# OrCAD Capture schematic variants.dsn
size A; title: EMA DESIGN AUTOMATION; rev: B; note: CIP DEMO
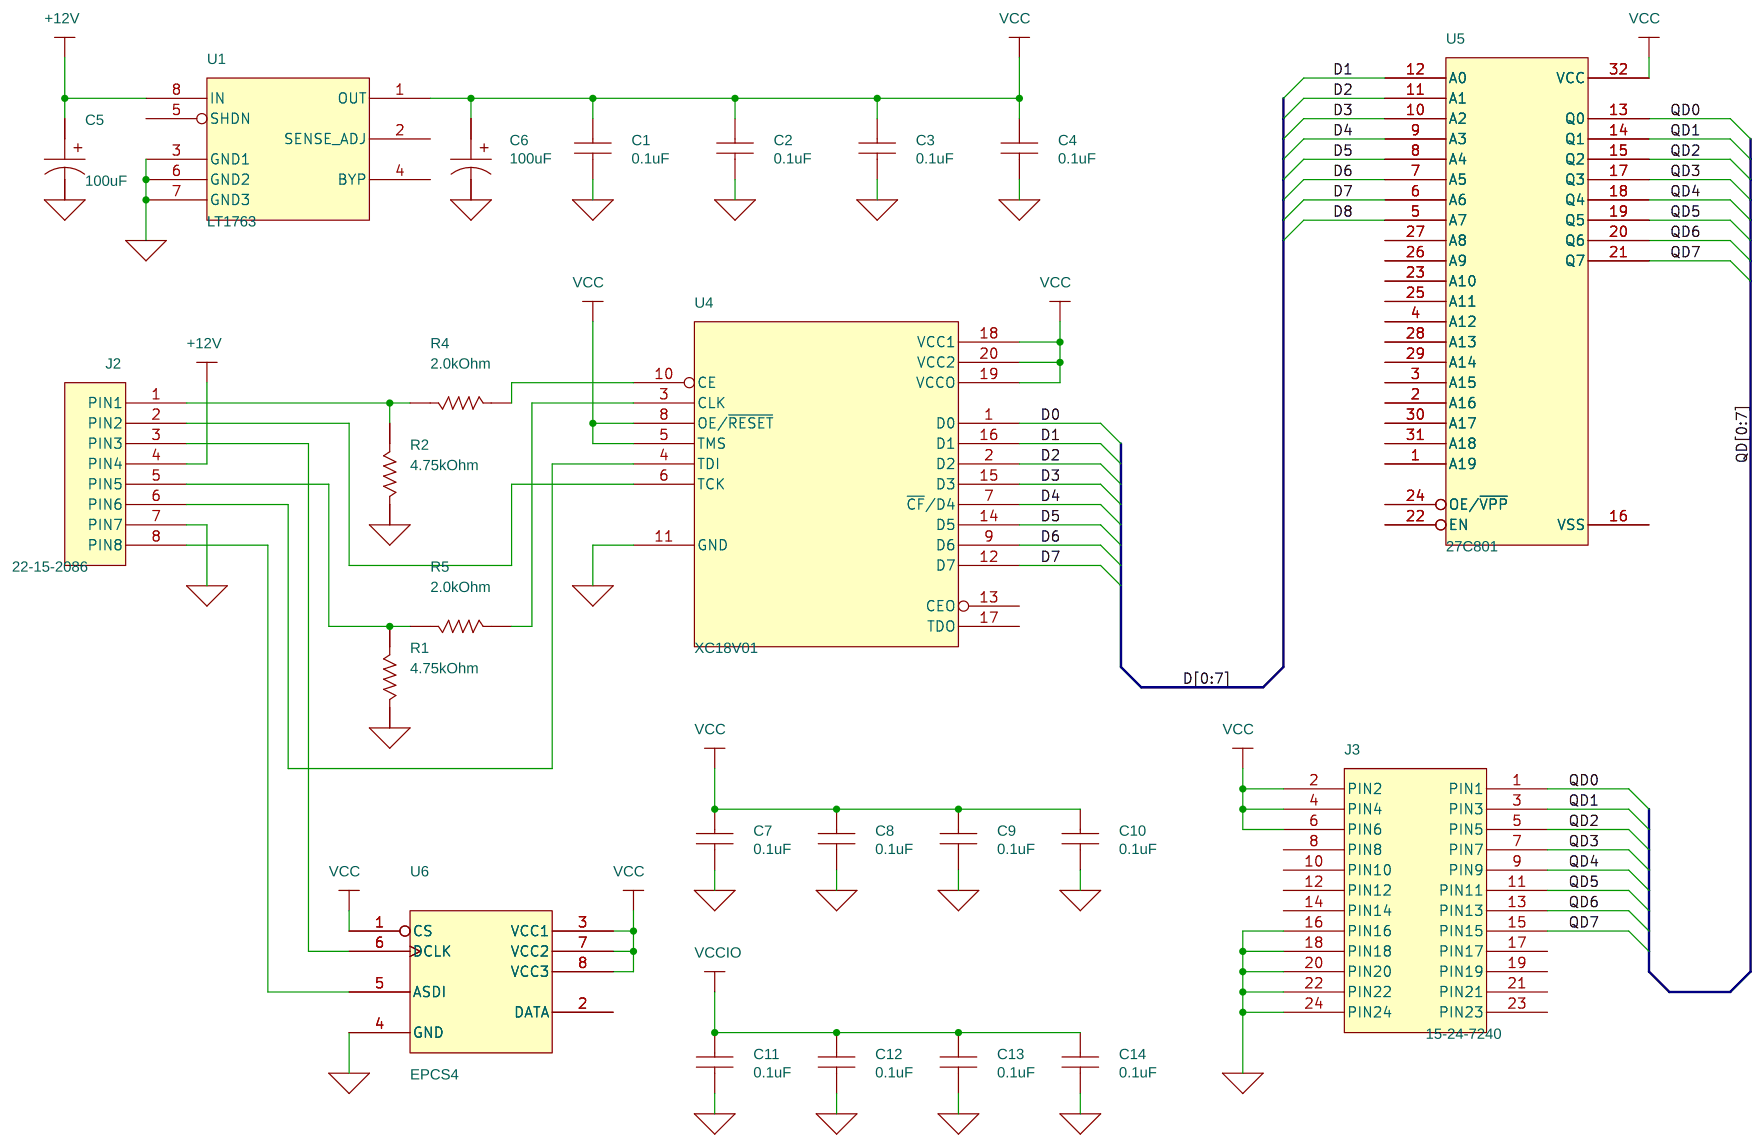
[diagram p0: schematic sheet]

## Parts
C1  0.1uF  [CAPC2012X71N]
C2  0.1uF  [CAPC2012X71N]
C3  0.1uF  [CAPC2012X71N]
C4  0.1uF  [CAPC2012X71N]
C5  100uF  [CAPMP6032X280N]
C6  100uF  [CAPMP6032X280N]
C7  0.1uF  [CAPC2012X71N]
C8  0.1uF  [CAPC2012X71N]
C9  0.1uF  [CAPC2012X71N]
C10  0.1uF  [CAPC2012X71N]
C11  0.1uF  [CAPC2012X71N]
C12  0.1uF  [CAPC2012X71N]
C13  0.1uF  [CAPC2012X71N]
C14  0.1uF  [CAPC2012X71N]
J2  22-15-2086  [MOLEX_4455A-8]
J3  15-24-7240  [MOLEX_42385-24]
R1  4.75kOhm  [RESC1608X55N]
R2  4.75kOhm  [RESC1608X55N]
R4  2.0kOhm  [RESC1608X55N]
R5  2.0kOhm  [RESC1608X55N]
U1  LT1763  [SOIC127P600X175-8N]
U4  XC18V01  [SOIC127P1034X267-20N]
U5  27C801  [DIP32-600]
U6  EPCS4  [SOIC127P600X175-8N]

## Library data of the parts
C1-C4 C7-C14 = CAP: CAP, Ceramic, SMD, 0.1 uF, 10 %, 25 V, 0805; CLASS: DISCRETE; Dielectric Type: Ceramic; Manufacturer: AVX; Manufacturer PN: 08053C104KAT2A; Operating Temperature Maximum: 125 C; Operating Temperature Minimum: -55 C; PART_NUMBER: EMA-00000403; Package Size: 0805; Rated Voltage: 25 V; Temperature Coefficient: X7R; Tolerance: 10%
C5 C6 = CAP_P: CAP, Tantalum, SMD, 100 uF, 10 %, 6.3 V, 6032-28; CLASS: DISCRETE; Dielectric Type: Tantalum; Manufacturer: AVX; Manufacturer PN: TPSC107K006R0150; Operating Temperature Maximum: 125 C; Operating Temperature Minimum: -55 C; PART_NUMBER: EMA-00000517; Package Size: 6032-28; Part Number: EMA-00007000; Rated Voltage: 6.3 V; Tolerance: 10%
J2 = CONN_PCB_1X8_F: CONN, Header, 22-15-2086, 8, TH; CLASS: IO; Contact Voltage: 250 V; Manufacturer: Molex Inc; Operating Temperature Maximum: 75 C; Operating Temperature Minimum: 0.0 C; PART_NUMBER: EMA-00006006; Package Size: 20.22 x 7.9 x 7.7 mm
J3 = HDR_2X12_F: CONN, Header, 15-24-7240, 24, TH; CLASS: IO; Contact Voltage: 600 V; Manufacturer: Molex Inc; Operating Temperature Maximum: 105 C; Operating Temperature Minimum: -40 C; PART_NUMBER: EMA-00005995; Package Size: 51.6 x 9.6 x 11.34 mm
R1 R2 = RES: RES, Thick Film, 4.75 kOhm, 1.0 %, 1/10 W, SMD, 0603; CLASS: DISCRETE; Manufacturer: Rohm; Manufacturer PN: MCR03EZPFX4751; Operating Temperature Maximum: 155 C; Operating Temperature Minimum: -55 C; PART_NUMBER: EMA-00003690; Package Size: 0603; Part Number: EMA-00004379; Rated Power: 1/10 W; Rated Voltage: 50 V; Temperature Coefficient: +/-100 ppm; Tolerance: 1.0%
R4 R5 = RES: RES, Thick Film, 2.0 kOhm, 5.0 %, 1/10 W, SMD, 0603; CLASS: DISCRETE; Manufacturer: Rohm; Manufacturer PN: MCR03EZPJ202; Operating Temperature Maximum: 155 C; Operating Temperature Minimum: -55 C; PART_NUMBER: EMA-00003600; Package Size: 0603; Part Number: EMA-00004192; Rated Power: 1/10 W; Rated Voltage: 50 V; Temperature Coefficient: +/-200 ppm; Tolerance: 5.0%
U1 = REG_1X_8P_LT1763: IC, Voltage Regulator, Linear-LDO, LT1763, SOIC-8; CLASS: IC; Manufacturer: Linear Technology; Manufacturer PN: LT1763CS8#PBF; Operating Temperature Maximum: 125 C; Operating Temperature Minimum: -40 C; PART_NUMBER: EMA-00006786; Package Size: SOIC-8; Supply Voltage: 1.8 - 20 V
U4 = XC18VXXXSO20: IC, Memory Devices, PROM, XC18V01, SOIC-20; CLASS: IC; Manufacturer: Xilinx; Manufacturer PN: XC18V01SOG20C; Operating Temperature Maximum: 85 C; Operating Temperature Minimum: -40 C; PART_NUMBER: EMA-00007402; Package Size: SOIC-20; Supply Voltage: 3.6 V
U5 = M27_CW_801_FBK: IC, Memory Devices, EEPROM, 27C801, DIP-32; CLASS: IC; Manufacturer: STMicroelectronics; Manufacturer PN: M27C801-100F1; Operating Temperature Maximum: 70 C; Operating Temperature Minimum: 0.0 C; PART_NUMBER: EMA-00007179; Package Size: DIP-32; Supply Voltage: 5.0 V
U6 = EPCSXXXX_8P: IC, Programmable Devices, Config Device, EPCS4, SOIC-8; CLASS: IC; Manufacturer: Altera Corporation; Manufacturer PN: EPCS4SI8N; Operating Temperature Maximum: 150 C; Operating Temperature Minimum: -65 C; PART_NUMBER: EMA-00006523; Package Size: SOIC-8; Rated Power: 54 mW; Supply Voltage: 3.3 V

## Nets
+12V: C5.1 J2.4(PIN4) U1.8(IN)
GND_SIGNAL: C1.2 C2.2 C3.2 C4.2 C5.2 C6.2 C7.2 C8.2 C9.2 C10.2 C11.2 C12.2 C13.2 C14.2 J2.7(PIN7) J3.16(PIN16) J3.18(PIN18) J3.20(PIN20) J3.22(PIN22) J3.24(PIN24) R1.2 R2.2 U1.3(GND1) U1.6(GND2) U1.7(GND3) U4.11(GND) U6.4(GND)
VCC: C1.1 C2.1 C3.1 C4.1 C6.1 C7.1 C8.1 C9.1 C10.1 J3.2(PIN2) J3.4(PIN4) J3.6(PIN6) U1.1(OUT) U4.5(TMS) U4.8(OE/~{RESET}) U4.18(VCC1) U4.19(VCCO) U4.20(VCC2) U5.32(VCC) U6.1(CS) U6.3(VCC1) U6.7(VCC2) U6.8(VCC3)
VCCIO: C11.1 C12.1 C13.1 C14.1
VSS: U5.16(VSS)
D0: U4.1(D0)
D1: U4.16(D1) U5.12(A0)
D2: U4.2(D2) U5.11(A1)
D3: U4.15(D3) U5.10(A2)
D4: U4.7(~{CF}/D4) U5.9(A3)
D5: U4.14(D5) U5.8(A4)
D6: U4.9(D6) U5.7(A5)
D7: U4.12(D7) U5.6(A6)
D8: U5.5(A7)
QD0: J3.1(PIN1) U5.13(Q0)
QD1: J3.3(PIN3) U5.14(Q1)
QD2: J3.5(PIN5) U5.15(Q2)
QD3: J3.7(PIN7) U5.17(Q3)
QD4: J3.9(PIN9) U5.18(Q4)
QD5: J3.11(PIN11) U5.19(Q5)
QD6: J3.13(PIN13) U5.20(Q6)
QD7: J3.15(PIN15) U5.21(Q7)
N00520: J2.5(PIN5) R1.1 R5.1
N00614: J2.1(PIN1) R2.1 R4.1
N02570: R4.2 U4.10(CE)
N02663: R5.2 U4.3(CLK)
N02853: J2.2(PIN2) U4.6(TCK)
N06329: J2.3(PIN3) U6.6(DCLK)
N11467: J2.6(PIN6) U4.4(TDI)
N139387: J2.8(PIN8) U6.5(ASDI)

Not connected (* = marked no-connect by the designer): J3 8(PIN8) 10(PIN10) 12(PIN12) 14(PIN14) 17(PIN17) 19(PIN19) 21(PIN21) 23(PIN23); U1 2(SENSE_ADJ) 4(BYP) 5(SHDN); U4 13(CEO) 17(TDO); U5 1(A19) 2(A16) 3(A15) 4(A12) 22(EN) 23(A10) 24(OE/~{VPP}) 25(A11) 26(A9) 27(A8) 28(A13) 29(A14) 30(A17) 31(A18); U6 2(DATA)
